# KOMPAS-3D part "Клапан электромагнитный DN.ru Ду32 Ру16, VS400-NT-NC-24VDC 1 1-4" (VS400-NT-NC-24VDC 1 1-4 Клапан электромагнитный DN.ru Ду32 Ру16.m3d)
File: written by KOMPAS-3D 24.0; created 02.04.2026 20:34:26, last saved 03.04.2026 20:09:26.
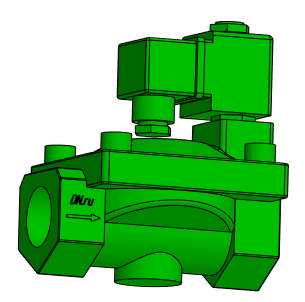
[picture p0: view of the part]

Document properties: Автор: artio; Полное имя файла: C:\Users\artio\OneDrive\Рабочий стол\Клапан электромагнитный DN.ru\VS400-NT-NC\VS400-NT-NC-24VDC 1 1-4 Клапан электромагнитный DN.ru Ду32 Ру16.m3d

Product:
- Body: Тело 1  | qty 1
    Масса: 4.144257
- Part/product: Клапан электромагнитный DN.ru Ду32 Ру16  | designation VS400-NT-NC-24VDC 1 1-4
    Масса: 2.569
    Раздел спецификации: Прочие изделия
    Примечание: D130-04729
    additional columns: ef56311e-7521-43dc-8291-0e6108b3d81d; VS400-ET-NC-220VAC 1 1-4; artio; c; Шероховатость не задана; Да

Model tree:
1. Операция без истории:1

Expressions: VS400-NT-NC-24VDC 1 1-4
